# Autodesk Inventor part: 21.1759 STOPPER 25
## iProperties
Created: 2007-03
Part Number: 21.1759 STOPPER 25
Document SubType Name: Modeling
Designer: Andy Moles
Material: Rubber
Mass: 7.11064 g
Surface Area: 23.4834 cm^2
Volume: 7.64585 cm^3
Density: 0.93 g/cm^3
Author: Andy Moles
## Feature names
1. Extrusion1
2. Extrusion2
